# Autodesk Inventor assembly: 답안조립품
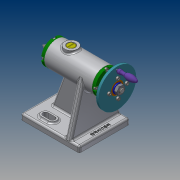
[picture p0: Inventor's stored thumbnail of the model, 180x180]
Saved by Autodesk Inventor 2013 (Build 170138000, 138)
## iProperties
Created: 2019-10
Part Number: 답안조립품
Document SubType Name: Assembly
Designer: user
Author: user
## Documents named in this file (18)
- C:\Users\user\Desktop\491004V1026\답안조립품.iam
- C:\Users\user\Desktop\491004V1026\본체.ipt
- C:\Users\user\Desktop\491004V1026\나사.ipt
- C:\Users\user\Desktop\491004V1026\나사축.ipt
- C:\Users\user\Desktop\491004V1026\너트 M8.ipt
- C:\Users\user\Desktop\491004V1026\돌림판.ipt
- C:\Users\user\Desktop\491004V1026\멈춤나사 M3.ipt
- C:\Users\user\Desktop\491004V1026\볼트 M3.ipt
- C:\Users\user\Desktop\491004V1026\부시.ipt
- C:\Users\user\Desktop\491004V1026\센터.ipt
- C:\Users\user\Desktop\491004V1026\센터홀더.ipt
- C:\Users\user\Desktop\491004V1026\슬리브.ipt
- C:\Users\user\Desktop\491004V1026\와셔.ipt
- C:\Users\user\Desktop\491004V1026\중공축.ipt
- C:\Users\user\Desktop\491004V1026\커버.ipt
- C:\Users\user\Desktop\491004V1026\키 4 x 4 x 10.ipt
- C:\Users\user\Desktop\491004V1026\플랜지.ipt
- C:\Users\user\Desktop\491004V1026\핸들.ipt
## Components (2 placed, 2 different names)
1. 플랜지:1
2. 핸들:1 — 플러쉬:3
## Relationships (1: Flush 1)
- 플러쉬:3 [Flush]: 핸들:1
